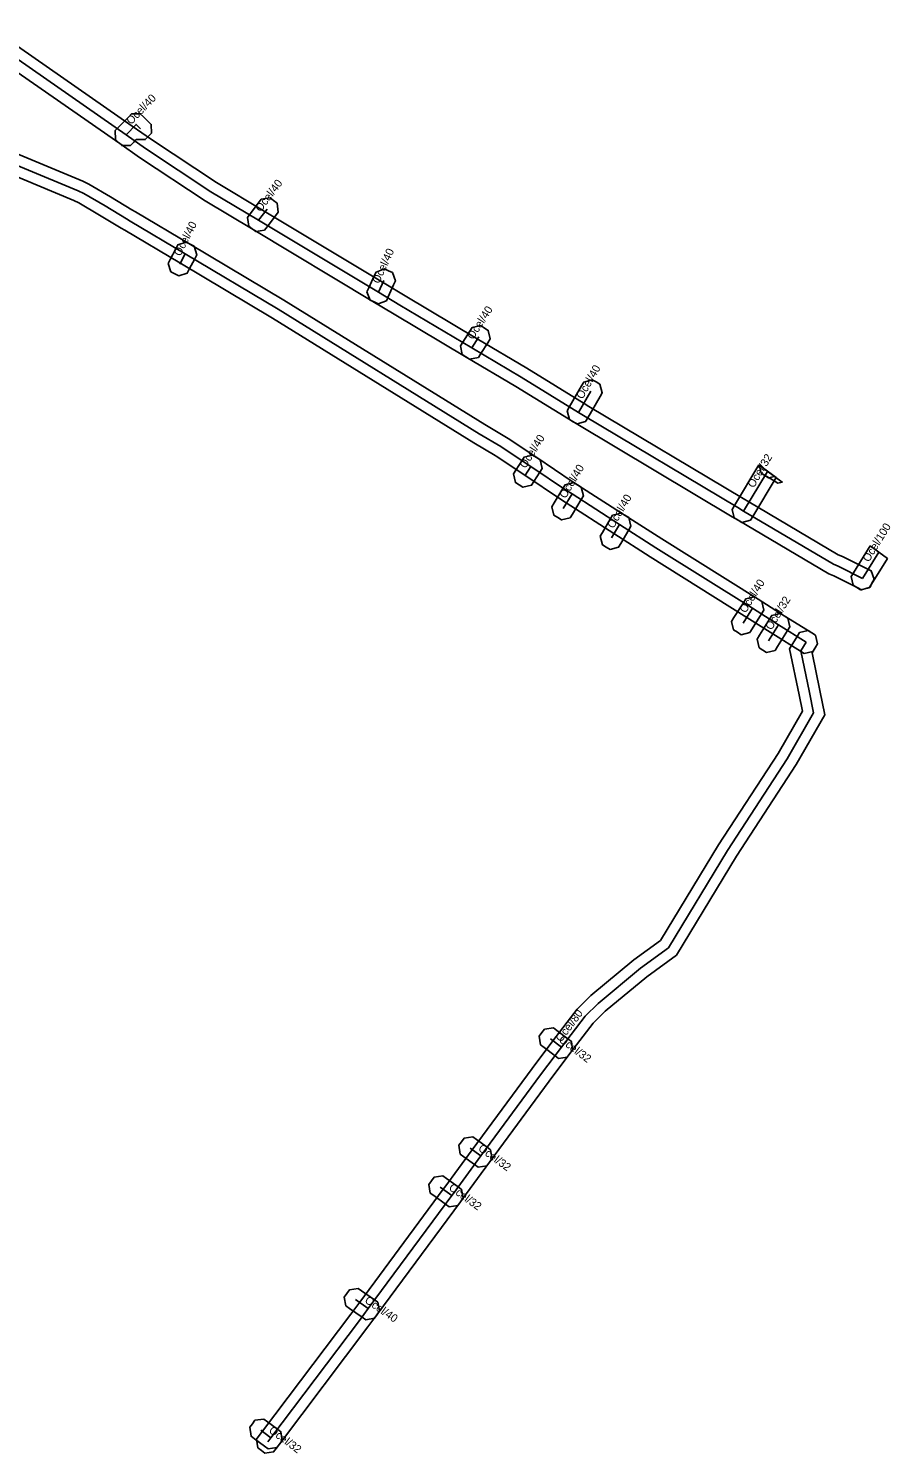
# Model space of a CAD drawing. Extents: x -600607 to -600238, y -1203924 to -1203617.
# Drawn here: x -600318.4 to -600237.6, y -1203802.3 to -1203668.7 of the extents above; entities that cross this region are included whole.
import ezdxf

# ---------------------------------------------------------------- set-up
doc = ezdxf.new("R2010")
doc.units = 0
for name, color, linetype in [('1', 7, 'Continuous'), ('14', 7, 'Continuous'), ('20', 7, 'Continuous')]:
    doc.layers.add(name, color=color, linetype=linetype)

msp = doc.modelspace()

# ---------------------------------------------------------------- linework, layer by layer
at = {"layer": '1'}
for points in [[(-600321.82, -1203668.7), (-600308.67, -1203677.85), (-600306.85, -1203679.12), (-600300.75, -1203683.15), (-600296.3, -1203685.82), (-600285.05, -1203692.57), (-600283.07, -1203693.77), (-600276.32, -1203697.78), (-600271.67, -1203700.53), (-600266.29, -1203703.85), (-600265.84, -1203704.14), (-600251.39, -1203712.75), (-600250.84, -1203713.08), (-600242.48, -1203718.03), (-600242.08, -1203718.19), (-600239.75, -1203719.36), (-600239.38, -1203719.54), (-600239.12, -1203720.33), (-600239.31, -1203720.7), (-600239.49, -1203721.07), (-600240.28, -1203721.33), (-600240.65, -1203721.14), (-600242.9, -1203720.01), (-600243.36, -1203719.83), (-600251.86, -1203714.8), (-600252.41, -1203714.47), (-600266.88, -1203705.84), (-600267.35, -1203705.55), (-600272.71, -1203702.25), (-600277.34, -1203699.5), (-600284.09, -1203695.49), (-600286.09, -1203694.29), (-600297.33, -1203687.54), (-600301.81, -1203684.85), (-600307.97, -1203680.78), (-600309.81, -1203679.49), (-600322.34, -1203670.78)], [(-600327.93, -1203676.92), (-600313.29, -1203683.01), (-600312.71, -1203683.3), (-600310.69, -1203684.48), (-600308.68, -1203685.69), (-600308.34, -1203685.89), (-600303.18, -1203688.96), (-600294.46, -1203694.16), (-600275.6, -1203705.83), (-600273.57, -1203707.04), (-600273.43, -1203707.14), (-600270.74, -1203708.93), (-600267.41, -1203711.16), (-600266.89, -1203711.5), (-600262.44, -1203714.36), (-600259.02, -1203716.56), (-600249.99, -1203722.21), (-600247.54, -1203723.75), (-600244.95, -1203725.37), (-600244.6, -1203725.59), (-600244.41, -1203726.4), (-600244.63, -1203726.75), (-600244.85, -1203727.1), (-600245.66, -1203727.29), (-600246.01, -1203727.07), (-600248.6, -1203725.45), (-600251.05, -1203723.91), (-600260.1, -1203718.24), (-600263.52, -1203716.04), (-600267.97, -1203713.18), (-600268.51, -1203712.84), (-600271.86, -1203710.59), (-600274.54, -1203708.8), (-600274.63, -1203708.74), (-600276.64, -1203707.54), (-600295.5, -1203695.86), (-600304.2, -1203690.68), (-600309.36, -1203687.61), (-600309.7, -1203687.41), (-600311.71, -1203686.2), (-600313.67, -1203685.06), (-600314.13, -1203684.83), (-600328.89, -1203678.68)]]:
    msp.add_lwpolyline(points, dxfattribs=at)
for points in [[(-600308.27, -1203679.12), (-600308.28, -1203679.12), (-600308.52, -1203679.37), (-600308.81, -1203679.66), (-600309.64, -1203679.68), (-600309.94, -1203679.39), (-600310.23, -1203679.1), (-600310.25, -1203678.27), (-600309.96, -1203677.97), (-600309.02, -1203677), (-600308.73, -1203676.71), (-600308.31, -1203676.7), (-600307.9, -1203676.69), (-600307.6, -1203676.99), (-600307.17, -1203677.41), (-600306.88, -1203677.69), (-600306.86, -1203678.52), (-600307.16, -1203678.82), (-600307.44, -1203679.11)], [(-600297.86, -1203686.41), (-600297.61, -1203686.07), (-600296.82, -1203685.03), (-600296.57, -1203684.71), (-600295.74, -1203684.59), (-600295.42, -1203684.84), (-600295.08, -1203685.09), (-600294.97, -1203685.92), (-600295.22, -1203686.25), (-600296.01, -1203687.28), (-600296.27, -1203687.61), (-600297.08, -1203687.73), (-600297.42, -1203687.48), (-600297.74, -1203687.23)], [(-600305.28, -1203690.72), (-600305.09, -1203690.35), (-600304.58, -1203689.36), (-600304.39, -1203688.99), (-600303.6, -1203688.74), (-600303.23, -1203688.93), (-600302.86, -1203689.12), (-600302.61, -1203689.91), (-600302.8, -1203690.28), (-600303.31, -1203691.27), (-600303.5, -1203691.64), (-600304.29, -1203691.89), (-600304.66, -1203691.7), (-600305.03, -1203691.51)], [(-600286.65, -1203693.39), (-600286.48, -1203693.01), (-600285.97, -1203691.9), (-600285.8, -1203691.53), (-600285.02, -1203691.24), (-600284.64, -1203691.41), (-600284.27, -1203691.58), (-600283.98, -1203692.36), (-600284.15, -1203692.74), (-600284.66, -1203693.85), (-600284.83, -1203694.22), (-600285.61, -1203694.51), (-600285.99, -1203694.34), (-600286.36, -1203694.17)], [(-600277.9, -1203698.45), (-600277.67, -1203698.1), (-600277.01, -1203697.08), (-600276.79, -1203696.73), (-600275.97, -1203696.55), (-600275.63, -1203696.78), (-600275.28, -1203697.01), (-600275.1, -1203697.81), (-600275.33, -1203698.16), (-600275.99, -1203699.18), (-600276.21, -1203699.53), (-600277.03, -1203699.71), (-600277.37, -1203699.48), (-600277.72, -1203699.26)], [(-600267.89, -1203704.56), (-600267.69, -1203704.2), (-600266.54, -1203702.21), (-600266.33, -1203701.85), (-600265.53, -1203701.64), (-600265.17, -1203701.84), (-600264.81, -1203702.05), (-600264.6, -1203702.85), (-600264.8, -1203703.21), (-600265.95, -1203705.2), (-600266.16, -1203705.56), (-600266.96, -1203705.77), (-600267.32, -1203705.57), (-600267.68, -1203705.36)], [(-600272.92, -1203710.46), (-600272.7, -1203710.11), (-600272.15, -1203709.23), (-600271.93, -1203708.88), (-600271.12, -1203708.69), (-600270.77, -1203708.91), (-600270.42, -1203709.13), (-600270.23, -1203709.94), (-600270.45, -1203710.29), (-600271, -1203711.17), (-600271.22, -1203711.52), (-600272.03, -1203711.71), (-600272.38, -1203711.49), (-600272.73, -1203711.27)], [(-600249.92, -1203709.62), (-600248.3, -1203710.8), (-600250.49, -1203714.46), (-600250.71, -1203714.81), (-600251.51, -1203715.01), (-600251.86, -1203714.8), (-600252.22, -1203714.58), (-600252.42, -1203713.78), (-600252.21, -1203713.43)], [(-600249.7, -1203710.39), (-600249.88, -1203709.65), (-600248.46, -1203710.69), (-600249, -1203710.82), (-600249.35, -1203710.6)], [(-600249.7, -1203710.39), (-600249.89, -1203709.65), (-600247.72, -1203711.23), (-600248.14, -1203711.33), (-600248.49, -1203711.12), (-600249.34, -1203710.61)], [(-600269.32, -1203713.54), (-600269.11, -1203713.18), (-600268.29, -1203711.82), (-600268.07, -1203711.47), (-600267.27, -1203711.27), (-600266.91, -1203711.48), (-600266.56, -1203711.7), (-600266.36, -1203712.5), (-600266.57, -1203712.86), (-600267.39, -1203714.22), (-600267.61, -1203714.57), (-600268.41, -1203714.77), (-600268.77, -1203714.56), (-600269.12, -1203714.34)], [(-600264.79, -1203716.31), (-600264.58, -1203715.95), (-600263.84, -1203714.69), (-600263.63, -1203714.34), (-600262.83, -1203714.13), (-600262.47, -1203714.34), (-600262.12, -1203714.55), (-600261.91, -1203715.35), (-600262.12, -1203715.71), (-600262.86, -1203716.97), (-600263.07, -1203717.32), (-600263.87, -1203717.53), (-600264.23, -1203717.32), (-600264.58, -1203717.11)], [(-600239.49, -1203717.21), (-600237.87, -1203718.39), (-600239.35, -1203720.78), (-600239.57, -1203721.13), (-600240.38, -1203721.32), (-600240.73, -1203721.1), (-600241.08, -1203720.88), (-600241.27, -1203720.07), (-600241.05, -1203719.72)], [(-600252.47, -1203724.28), (-600252.25, -1203723.93), (-600251.37, -1203722.53), (-600251.15, -1203722.18), (-600250.34, -1203721.99), (-600249.99, -1203722.21), (-600249.64, -1203722.43), (-600249.45, -1203723.24), (-600249.67, -1203723.59), (-600250.55, -1203724.99), (-600250.77, -1203725.34), (-600251.58, -1203725.53), (-600251.93, -1203725.31), (-600252.28, -1203725.09)], [(-600250.09, -1203725.94), (-600249.87, -1203725.59), (-600248.92, -1203724.07), (-600248.7, -1203723.72), (-600247.89, -1203723.53), (-600247.54, -1203723.75), (-600247.19, -1203723.97), (-600247, -1203724.78), (-600247.22, -1203725.13), (-600248.17, -1203726.65), (-600248.39, -1203727), (-600249.2, -1203727.19), (-600249.55, -1203726.97), (-600249.9, -1203726.75)], [(-600297, -1203800.94), (-600296.75, -1203800.61), (-600296.45, -1203800.21), (-600288.16, -1203789.22), (-600287.33, -1203788.1), (-600279.5, -1203777.51), (-600279.35, -1203777.31), (-600276.79, -1203773.81), (-600271.18, -1203766.19), (-600269.22, -1203763.6), (-600266.96, -1203760.64), (-600265.66, -1203759.36), (-600261.64, -1203756.02), (-600259.15, -1203754.2), (-600253.71, -1203745.24), (-600248.11, -1203736.66), (-600245.84, -1203732.69), (-600246.15, -1203731.16), (-600247.05, -1203726.85), (-600246.33, -1203725.69), (-600246.11, -1203725.34), (-600245.3, -1203725.15), (-600244.95, -1203725.37), (-600244.6, -1203725.59), (-600244.41, -1203726.4), (-600244.63, -1203726.75), (-600244.93, -1203727.23), (-600244.19, -1203730.76), (-600243.72, -1203733.03), (-600246.41, -1203737.7), (-600252.01, -1203746.3), (-600257.65, -1203755.58), (-600260.41, -1203757.6), (-600264.32, -1203760.84), (-600265.46, -1203761.96), (-600267.62, -1203764.81), (-600269.58, -1203767.39), (-600275.17, -1203774.99), (-600277.75, -1203778.51), (-600277.9, -1203778.71), (-600285.73, -1203789.29), (-600286.56, -1203790.42), (-600294.85, -1203801.41), (-600295.15, -1203801.81), (-600295.4, -1203802.14), (-600296.22, -1203802.26), (-600296.55, -1203802.01), (-600296.88, -1203801.76)], [(-600269.18, -1203762.38), (-600268.85, -1203762.63), (-600267.82, -1203763.41), (-600267.49, -1203763.66), (-600267.37, -1203764.48), (-600267.62, -1203764.81), (-600267.87, -1203765.14), (-600268.69, -1203765.26), (-600269.02, -1203765.01), (-600270.05, -1203764.23), (-600270.38, -1203763.98), (-600270.5, -1203763.16), (-600270.25, -1203762.83), (-600270, -1203762.5)], [(-600276.73, -1203772.61), (-600276.4, -1203772.85), (-600275.39, -1203773.59), (-600275.06, -1203773.84), (-600274.93, -1203774.66), (-600275.17, -1203774.99), (-600275.42, -1203775.32), (-600276.24, -1203775.45), (-600276.57, -1203775.21), (-600277.58, -1203774.47), (-600277.92, -1203774.22), (-600278.04, -1203773.4), (-600277.8, -1203773.07), (-600277.55, -1203772.74)], [(-600279.55, -1203776.26), (-600279.21, -1203776.5), (-600278.11, -1203777.3), (-600277.78, -1203777.54), (-600277.65, -1203778.36), (-600277.89, -1203778.7), (-600278.14, -1203779.03), (-600278.95, -1203779.16), (-600279.29, -1203778.92), (-600280.39, -1203778.12), (-600280.72, -1203777.88), (-600280.85, -1203777.06), (-600280.61, -1203776.72), (-600280.36, -1203776.39)], [(-600287.49, -1203786.81), (-600287.15, -1203787.05), (-600285.96, -1203787.88), (-600285.62, -1203788.12), (-600285.47, -1203788.93), (-600285.71, -1203789.27), (-600285.95, -1203789.61), (-600286.76, -1203789.76), (-600287.1, -1203789.52), (-600288.29, -1203788.69), (-600288.63, -1203788.45), (-600288.78, -1203787.64), (-600288.54, -1203787.3), (-600288.3, -1203786.96)], [(-600296.33, -1203799.06), (-600295.99, -1203799.31), (-600295.05, -1203800.01), (-600294.72, -1203800.26), (-600294.6, -1203801.07), (-600294.85, -1203801.41), (-600295.09, -1203801.74), (-600295.92, -1203801.86), (-600296.25, -1203801.61), (-600297.19, -1203800.91), (-600297.52, -1203800.67), (-600297.64, -1203799.84), (-600297.39, -1203799.51), (-600297.15, -1203799.18)]]:
    msp.add_lwpolyline(points, close=True, dxfattribs=at)
at = {"layer": '14'}
for points in [[(-600240.2, -1203720.25), (-600242.49, -1203719.1), (-600242.92, -1203718.93), (-600251.35, -1203713.94), (-600251.9, -1203713.61), (-600266.36, -1203704.99), (-600266.82, -1203704.7), (-600272.19, -1203701.39), (-600276.83, -1203698.64), (-600283.58, -1203694.63), (-600285.57, -1203693.43), (-600296.81, -1203686.68), (-600301.28, -1203684), (-600307.41, -1203679.95), (-600309.24, -1203678.67), (-600322.08, -1203669.74)], [(-600328.46, -1203677.78), (-600313.71, -1203683.92), (-600313.19, -1203684.18), (-600311.2, -1203685.34), (-600309.19, -1203686.55), (-600308.85, -1203686.75), (-600303.69, -1203689.82), (-600294.98, -1203695.01), (-600276.12, -1203706.69), (-600274.1, -1203707.89), (-600273.98, -1203707.97), (-600271.3, -1203709.76), (-600267.96, -1203712), (-600267.43, -1203712.34), (-600262.98, -1203715.2), (-600259.56, -1203717.4), (-600250.52, -1203723.06), (-600248.07, -1203724.6), (-600245.48, -1203726.22)], [(-600309.24, -1203678.67), (-600308.3, -1203677.7), (-600307.87, -1203678.12)], [(-600296.81, -1203686.68), (-600296.02, -1203685.64)], [(-600304.2, -1203690.81), (-600303.69, -1203689.82)], [(-600285.57, -1203693.43), (-600285.06, -1203692.32)], [(-600276.83, -1203698.64), (-600276.17, -1203697.62)], [(-600266.82, -1203704.7), (-600265.67, -1203702.71)], [(-600271.85, -1203710.64), (-600271.3, -1203709.76)], [(-600251.35, -1203713.94), (-600249.11, -1203710.22)], [(-600268.25, -1203713.7), (-600267.43, -1203712.34)], [(-600263.72, -1203716.46), (-600262.98, -1203715.2)], [(-600240.2, -1203720.25), (-600238.68, -1203717.8)], [(-600251.4, -1203724.46), (-600250.52, -1203723.06)], [(-600249.02, -1203726.12), (-600248.07, -1203724.6)], [(-600295.95, -1203801.21), (-600295.65, -1203800.81), (-600287.36, -1203789.82), (-600286.53, -1203788.7), (-600278.7, -1203778.11), (-600278.55, -1203777.91), (-600275.98, -1203774.4), (-600270.38, -1203766.79), (-600268.42, -1203764.21), (-600266.21, -1203761.3), (-600264.99, -1203760.1), (-600261.02, -1203756.81), (-600258.4, -1203754.89), (-600252.86, -1203745.77), (-600247.26, -1203737.18), (-600244.78, -1203732.86), (-600245.17, -1203730.96), (-600245.99, -1203727.04), (-600245.48, -1203726.22)], [(-600269.45, -1203763.43), (-600268.42, -1203764.21)], [(-600276.99, -1203773.66), (-600275.98, -1203774.4)], [(-600279.8, -1203777.31), (-600278.7, -1203778.11)], [(-600287.72, -1203787.87), (-600286.53, -1203788.7)], [(-600296.59, -1203800.11), (-600295.65, -1203800.81)]]:
    msp.add_lwpolyline(points, dxfattribs=at)

# ---------------------------------------------------------------- texts
at = {"layer": '20'}
for s, rotation, p in [('Ocel/40', 45.8999, (-600308.76, -1203677.77)), ('Ocel/40', 52.7791, (-600296.61, -1203685.96)), ('Ocel/40', 62.7447, (-600304.15, -1203690.11)), ('Ocel/40', 65.3231, (-600285.52, -1203692.68)), ('Ocel/40', 57.0948, (-600276.7, -1203697.93)), ('Ocel/40', 59.9768, (-600266.45, -1203703.51)), ('Ocel/40', 57.9946, (-600271.78, -1203710)), ('Ocel/40', 58.9125, (-600268.04, -1203712.82)), ('Ocel/32', 58.976, (-600250.4, -1203711.83)), ('Ocel/40', 59.5742, (-600263.55, -1203715.63)), ('Ocel/100', 58.2293, (-600239.61, -1203718.78)), ('Ocel/40', 57.8477, (-600251.16, -1203723.56)), ('Ocel/32', 57.9946, (-600248.74, -1203725.16)), ('Ocel/80', 52.7851, (-600268.45, -1203763.78)), ('Ocel/32', 322.864, (-600268.74, -1203763.62)), ('Ocel/32', 323.7708, (-600276.29, -1203773.83)), ('Ocel/32', 323.9726, (-600279.05, -1203777.51)), ('Ocel/40', 325.105, (-600286.93, -1203788.08)), ('Ocel/32', 323.3257, (-600295.92, -1203800.26))]:
    msp.add_text(s, height=0.75, rotation=rotation, dxfattribs=at).set_placement(p)

doc.saveas('drawing.dxf')
